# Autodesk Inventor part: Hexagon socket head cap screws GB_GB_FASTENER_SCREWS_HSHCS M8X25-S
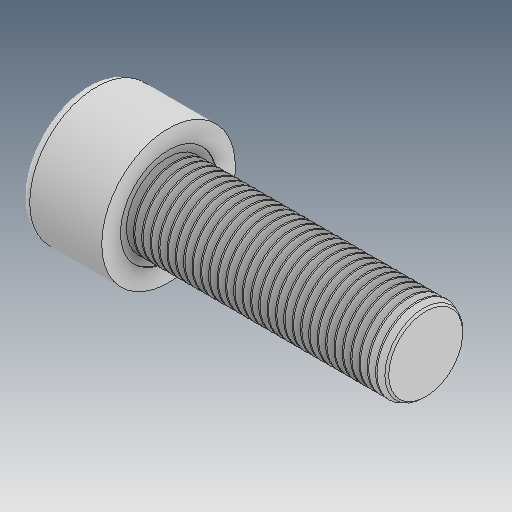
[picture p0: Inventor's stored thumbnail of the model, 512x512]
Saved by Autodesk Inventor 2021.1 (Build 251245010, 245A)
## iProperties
Created: 2013-04
Part Number: Hexagon socket head cap screws GB_GB_FASTENER_SCREWS_HSHCS M8X25-S
Material: Ogólny
Document SubType Name: Modeling
Designer: user
Density: 1 g/cm^3
Appearance: Domyślna
Author: user
Revision Number: ÈÎºÎ
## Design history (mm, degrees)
feature "LPattern10"
node "Bryła1"
